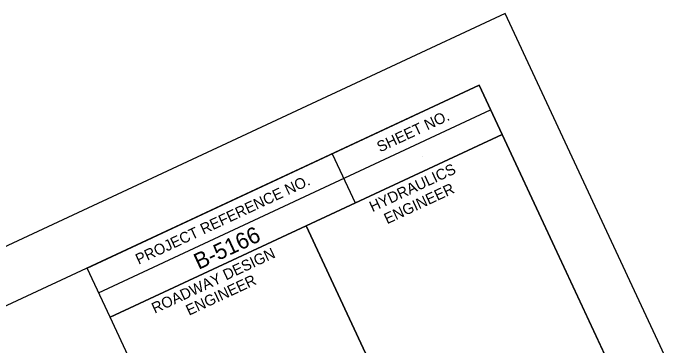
# Model space of a CAD drawing. Extents: x 2216017 to 2218023, y 761241 to 762957.
# Drawn here: x 2217330.4 to 2217640.8, y 762803 to 762956.6 of the extents above; entities that cross this region are included whole.
import ezdxf

# ---------------------------------------------------------------- set-up
doc = ezdxf.new("R2010")
doc.units = 0
for name, color, linetype in [('Scratch_Level_0', 7, 'Continuous'), ('Sheet Data Field CELL', 7, 'Continuous'), ('Sheet Plan And Profile CELL', 7, 'Continuous'), ('Stewart Plot Border Xerox6279 and LJ5000', 7, 'Continuous')]:
    doc.layers.add(name, color=color, linetype=linetype)

msp = doc.modelspace()

# ---------------------------------------------------------------- linework, layer by layer
at = {"layer": 'Scratch_Level_0'}
msp.add_line((2217519.75, 762890.47), (2217519.75, 762890.47), dxfattribs=at)
at = {"layer": 'Sheet Plan And Profile CELL'}
for p, q in [((2217369.79, 762827.44), (2217551.09, 762911.98)), ((2217477.84, 762891.61), (2217488.4, 762868.95)), ((2217465.74, 762858.39), (2217513.27, 762756.48))]:
    msp.add_line(p, q, dxfattribs=at)
for points in [[(2217545.79, 762923.35), (2216186.33, 762289.43), (2216630.08, 761337.8), (2217989.54, 761971.73)], [(2217364.48, 762838.81), (2217545.79, 762923.35), (2217556.38, 762900.65), (2217375.07, 762816.11)], [(2217465.74, 762858.39), (2217556.38, 762900.65), (2217603.92, 762798.69), (2217513.29, 762756.43)], [(2217375.07, 762816.11), (2217465.74, 762858.39), (2217513.29, 762756.43), (2217422.61, 762714.15)]]:
    msp.add_lwpolyline(points, close=True, dxfattribs=at)
at = {"layer": 'Stewart Plot Border Xerox6279 and LJ5000'}
msp.add_lwpolyline([(2216482.04, 761241.19), (2218022.76, 761959.64), (2217557.88, 762956.58), (2216017.16, 762238.13)], close=True, dxfattribs=at)

# ---------------------------------------------------------------- texts
at = {"layer": 'Sheet Data Field CELL'}
msp.add_text('B-5166', height=7.5, rotation=25, dxfattribs=at).set_placement((2217416.03, 762837.94))
at = {"layer": 'Sheet Plan And Profile CELL'}
for s, height, p in [('SHEET NO.', 5, (2217499.93, 762892.26)), ('HYDRAULICS', 5, (2217496.43, 762864.64)), ('PROJECT REFERENCE NO.', 5.0001, (2217388.28, 762840.31)), ('ENGINEER', 5, (2217503.23, 762859.04)), ('ROADWAY DESIGN', 5.0001, (2217395.74, 762817.69)), ('ENGINEER', 5, (2217411.57, 762816.74))]:
    msp.add_text(s, height=height, rotation=25, dxfattribs=at).set_placement(p)

doc.saveas('drawing.dxf')
